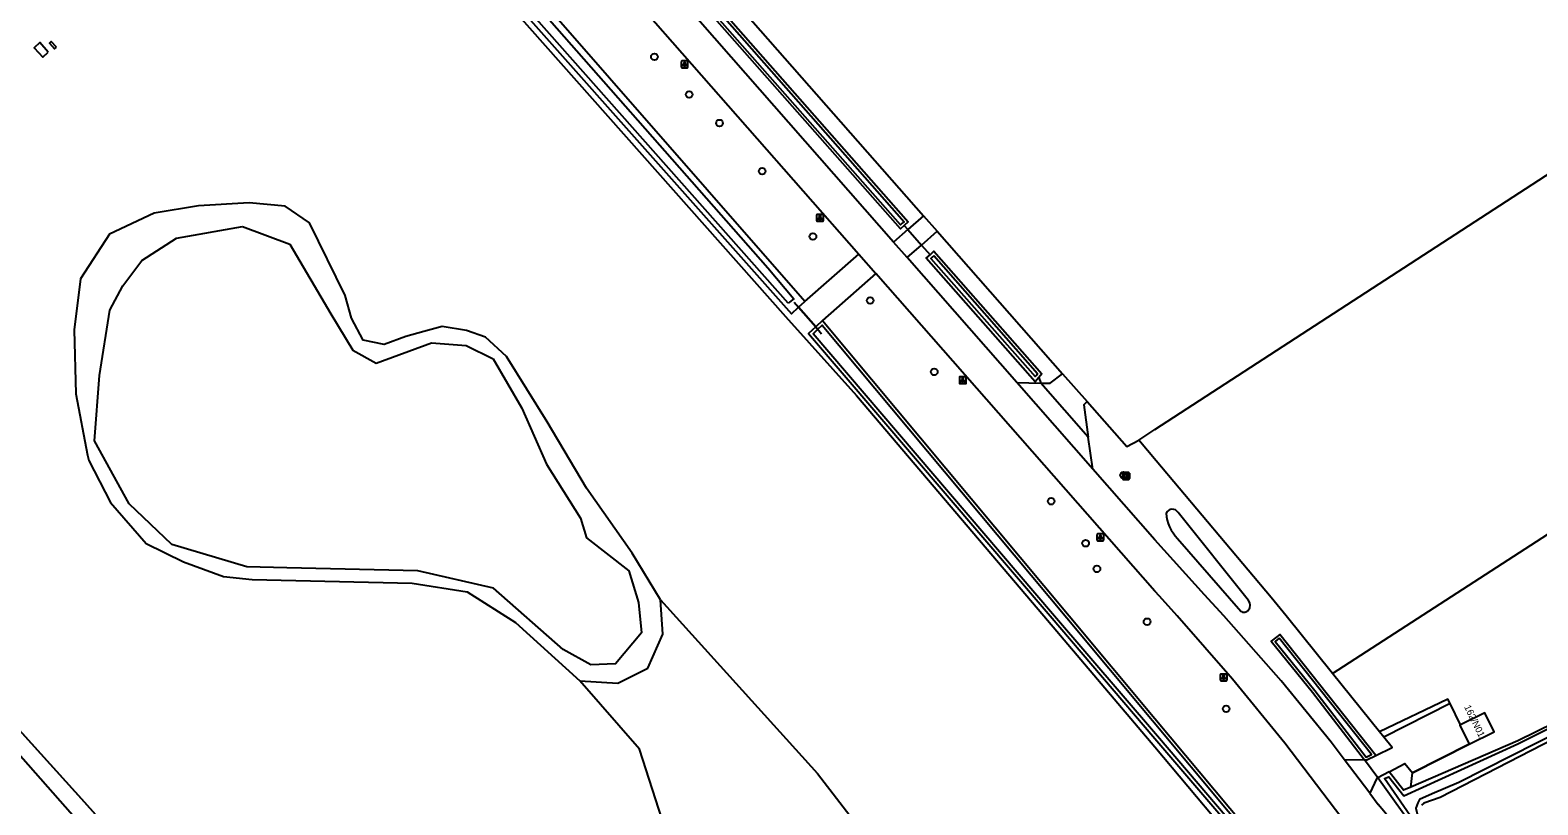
# Model space of a CAD drawing. Extents: x 156061 to 157804, y 383451 to 385640.
# Drawn here: x 157335.7 to 157555.9, y 383972.4 to 384085.5 of the extents above; entities that cross this region are included whole.
import ezdxf

# ---------------------------------------------------------------- set-up
doc = ezdxf.new("R2010")
doc.units = 0
for name, color, linetype in [('IMGEO_Berm_groen', 7, 'Continuous'), ('IMGEO_Boom', 7, 'Continuous'), ('IMGEO_Duiker', 7, 'Continuous'), ('IMGEO_Grasland_overig', 7, 'Continuous'), ('IMGEO_Groenvoorziening', 7, 'Continuous'), ('IMGEO_Haag', 7, 'Continuous'), ('IMGEO_Hek', 7, 'Continuous'), ('IMGEO_Lichtpunt', 7, 'Continuous'), ('IMGEO_Loofbos', 7, 'Continuous'), ('IMGEO_Meer_plas_ven_vijver', 7, 'Continuous'), ('IMGEO_Naaldbos', 7, 'Continuous'), ('IMGEO_Pand', 7, 'Continuous'), ('IMGEO_Pand_nummerreeks', 7, 'Continuous'), ('IMGEO_Rijbaan_lokaal_gesloten', 7, 'Continuous'), ('IMGEO_Rijbaan_lokaal_open', 7, 'Continuous'), ('IMGEO_Verklikker', 7, 'Continuous'), ('IMGEO_Waterloop', 7, 'Continuous')]:
    doc.layers.add(name, color=color, linetype=linetype)

msp = doc.modelspace()

# ---------------------------------------------------------------- linework, layer by layer
at = {"layer": 'IMGEO_Berm_groen'}
for points in [[(157463.38, 384056.98), (157462.83, 384056.5), (157343.68, 384191.47)], [(157317.96, 384189.64), (157344.19, 384159.18), (157364.55, 384136), (157393.61, 384102.92), (157399.11, 384096.66), (157446.05, 384043.69), (157456.41, 384032.18), (157483.79, 384000), (157500, 383980.87), (157519.27, 383957.9)], [(157448.89, 384045.9), (157391.84, 384111.13), (157390.82, 384110.23), (157389.32, 384108.91), (157446.91, 384044.08), (157447.97, 384045.05)], [(157463.38, 384056.98), (157463.91, 384056.38)], [(157463.91, 384056.38), (157461.84, 384054.56)], [(157463.91, 384056.38), (157465.9, 384054.13)], [(157448.89, 384045.9), (157456.76, 384052.82)], [(157463.82, 384052.3), (157465.9, 384054.13)], [(157465.9, 384054.13), (157467.16, 384052.71)], [(157483.03, 384034.79), (157482.52, 384034.17), (157466.6, 384052.22), (157467.16, 384052.71)], [(157459.26, 384049.98), (157451.47, 384043.13)], [(157450.46, 384042.19), (157447.97, 384045.05)], [(157450.46, 384042.19), (157449.42, 384041.22), (157484.69, 384000), (157500, 383982.12), (157520.38, 383958.3)], [(157451.47, 384043.13), (157487.5, 384000), (157500, 383985.04), (157521.88, 383958.85), (157530.15, 383962.42), (157532.92, 383958.91), (157532.95, 383957.92), (157532.22, 383957.33), (157531.69, 383956.9), (157531.35, 383957.26)], [(157479.83, 384034.07), (157483.33, 384033.99)], [(157483.03, 384034.79), (157483.33, 384033.99)], [(157490.28, 384026.1), (157483.33, 384033.99)], [(157490.12, 384031.28), (157489.62, 384030.82), (157490.28, 384026.1)], [(157490.12, 384031.28), (157495.9, 384024.71), (157497.66, 384025.67)], [(157490.93, 384021.43), (157490.28, 384026.1)], [(157525.95, 383991.61), (157519.18, 384000), (157517.01, 384002.7), (157500.2, 384022.65), (157497.66, 384025.67)], [(157532.29, 383979.64), (157518.23, 383997.3), (157516.98, 383996.33), (157523.02, 383988.86), (157530.64, 383978.98)], [(157532.83, 383983.08), (157525.95, 383991.61)]]:
    msp.add_lwpolyline(points, dxfattribs=at)
at = {"layer": 'IMGEO_Boom'}
for centre in [(157426.9, 384081.61), (157431.99, 384076.11), (157436.42, 384071.94), (157442.64, 384064.91), (157450.06, 384055.38), (157458.43, 384046.03), (157467.78, 384035.61), (157495.43, 384020.55), (157484.85, 384016.73), (157489.89, 384010.6), (157491.54, 384006.85), (157498.86, 383999.15), (157510.42, 383986.43)]:
    msp.add_circle(centre, 0.489, dxfattribs=at)
at = {"layer": 'IMGEO_Duiker'}
msp.add_lwpolyline([(157447.34, 384045.77), (157447.97, 384045.05), (157450.46, 384042.19), (157451.33, 384041.19)], dxfattribs=at)
at = {"layer": 'IMGEO_Grasland_overig'}
for points in [[(157466.22, 384058.41), (157463.91, 384056.38)], [(157466.22, 384058.41), (157468.2, 384056.16)], [(157465.9, 384054.13), (157468.2, 384056.16)], [(157447.97, 384045.05), (157448.89, 384045.9)], [(157451.47, 384043.13), (157450.46, 384042.19)], [(157483.33, 384033.99), (157484.7, 384033.96), (157486.53, 384035.35)], [(157486.53, 384035.35), (157490.12, 384031.28)]]:
    msp.add_lwpolyline(points, dxfattribs=at)
at = {"layer": 'IMGEO_Groenvoorziening'}
for points in [[(157375.38, 384222.59), (157376.59, 384220.76), (157342.51, 384199.14), (157412.58, 384119.43), (157466.22, 384058.41)], [(157344.9, 384192.66), (157463.98, 384057.5), (157463.38, 384056.98)], [(157497.66, 384025.67), (157500, 384027.19), (157642, 384119.41), (157643.26, 384117.4), (157752.8, 384188.65)], [(157338.37, 384082.3), (157337.13, 384083.67), (157336.32, 384082.91), (157337.56, 384081.55), (157338.37, 384082.3)], [(157339.56, 384083), (157338.8, 384083.82), (157338.55, 384083.59), (157339.31, 384082.77), (157339.56, 384083)], [(157525.95, 383991.61), (157642.66, 384067.03)], [(157427.78, 384002.36), (157423.67, 384009.14), (157417, 384018.64), (157411.26, 384028.33), (157405.29, 384037.84), (157402.23, 384040.67), (157399.47, 384041.67), (157395.89, 384042.26), (157393.24, 384041.49), (157390.58, 384040.79), (157387.45, 384039.61), (157384.39, 384040.23), (157382.66, 384043.44), (157381.76, 384046.77), (157376.54, 384057.37), (157372.96, 384059.82), (157367.71, 384060.27), (157360.32, 384059.84), (157353.83, 384058.77), (157347.34, 384055.73), (157343.08, 384049.2), (157342.15, 384041.74), (157342.41, 384032.41), (157344.13, 384023.44), (157344.28, 384022.68), (157347.47, 384016.55), (157352.67, 384010.55), (157358.11, 384007.87), (157363.98, 384005.74), (157368.14, 384005.33), (157391.54, 384004.75), (157399.57, 384003.53), (157406.64, 383999.04), (157416.03, 383990.5)], [(157468.2, 384056.16), (157486.53, 384035.35)], [(157467.16, 384052.71), (157467.74, 384053.23), (157483.49, 384035.34), (157483.03, 384034.79)], [(157656.19, 384033.53), (157590.21, 384000), (157553.01, 383981.76), (157549.75, 383980.34), (157537.39, 383975.02)], [(157656.19, 384033.53), (157656.8, 384032.66), (157593.24, 384000), (157541.68, 383973.51), (157539.29, 383972.68), (157538.96, 383972.37)], [(157542, 383963.16), (157538.56, 383967.99), (157532.58, 383976.37)], [(157537.39, 383975.02), (157536.33, 383974.56), (157534.2, 383977.23)], [(157537.39, 383975.02), (157537.64, 383977.09)]]:
    msp.add_lwpolyline(points, dxfattribs=at)
at = {"layer": 'IMGEO_Haag'}
for points in [[(157543.11, 383987.19), (157542.78, 383987.84), (157532.83, 383983.08)], [(157533.45, 383982.31), (157532.83, 383983.08)]]:
    msp.add_lwpolyline(points, dxfattribs=at)
at = {"layer": 'IMGEO_Hek'}
for points in [[(157376.59, 384220.76), (157342.51, 384199.14), (157412.58, 384119.43), (157466.22, 384058.41)], [(157500, 384027.19), (157642, 384119.41)], [(157466.22, 384058.41), (157468.2, 384056.16)], [(157468.2, 384056.16), (157486.53, 384035.35)], [(157286.32, 384037.05), (157293.19, 384028.12), (157297.01, 384023.54), (157304.07, 384015.72), (157311.43, 384008.18), (157319.02, 384000), (157343.68, 383972.81), (157358.66, 383956.01), (157373.77, 383939.34), (157386.41, 383926.07), (157399.25, 383913.04)], [(157486.53, 384035.35), (157490.12, 384031.28)], [(157490.12, 384031.28), (157495.9, 384024.71)], [(157497.66, 384025.67), (157500, 384027.19)], [(157495.9, 384024.71), (157497.66, 384025.67)], [(157500.2, 384022.65), (157497.66, 384025.67)], [(157519.18, 384000), (157517.01, 384002.7), (157500.2, 384022.65)], [(157525.95, 383991.61), (157519.18, 384000)], [(157532.83, 383983.08), (157525.95, 383991.61)], [(157543.11, 383987.19), (157542.78, 383987.84), (157532.83, 383983.08)], [(157544.65, 383984.1), (157543.11, 383987.19)], [(157545.89, 383981.26), (157537.64, 383977.09)]]:
    msp.add_lwpolyline(points, dxfattribs=at)
at = {"layer": 'IMGEO_Lichtpunt'}
for p, q in [((157430.82, 384080.92), (157430.82, 384080.11)), ((157430.82, 384080.92), (157430.82, 384080.11)), ((157431.72, 384081.01), (157430.91, 384081.01)), ((157431.72, 384081.01), (157430.91, 384081.01)), ((157430.91, 384080.01), (157431.72, 384080.01)), ((157430.91, 384080.01), (157431.72, 384080.01)), ((157431.81, 384080.11), (157431.81, 384080.92)), ((157431.81, 384080.11), (157431.81, 384080.92)), ((157450.59, 384058.51), (157450.59, 384057.7)), ((157450.59, 384058.51), (157450.59, 384057.7)), ((157451.49, 384058.61), (157450.69, 384058.61)), ((157451.49, 384058.61), (157450.69, 384058.61)), ((157450.69, 384057.61), (157451.49, 384057.61)), ((157450.69, 384057.61), (157451.49, 384057.61)), ((157451.59, 384057.7), (157451.59, 384058.51)), ((157451.59, 384057.7), (157451.59, 384058.51)), ((157472.35, 384034.91), (157471.54, 384034.91)), ((157472.35, 384034.91), (157471.54, 384034.91)), ((157471.45, 384034.81), (157471.45, 384034)), ((157471.45, 384034.81), (157471.45, 384034)), ((157471.54, 384033.91), (157472.35, 384033.91)), ((157471.54, 384033.91), (157472.35, 384033.91)), ((157472.44, 384034), (157472.44, 384034.81)), ((157472.44, 384034), (157472.44, 384034.81)), ((157491.53, 384011.88), (157491.53, 384011.07)), ((157491.53, 384011.88), (157491.53, 384011.07)), ((157492.43, 384011.97), (157491.63, 384011.97)), ((157492.43, 384011.97), (157491.63, 384011.97)), ((157491.63, 384010.97), (157492.43, 384010.97)), ((157491.63, 384010.97), (157492.43, 384010.97)), ((157492.53, 384011.07), (157492.53, 384011.88)), ((157492.53, 384011.07), (157492.53, 384011.88)), ((157509.55, 383991.41), (157509.55, 383990.61)), ((157509.55, 383991.41), (157509.55, 383990.61)), ((157510.45, 383991.51), (157509.64, 383991.51)), ((157510.45, 383991.51), (157509.64, 383991.51)), ((157510.55, 383990.61), (157510.55, 383991.41)), ((157510.55, 383990.61), (157510.55, 383991.41)), ((157509.64, 383990.51), (157510.45, 383990.51)), ((157509.64, 383990.51), (157510.45, 383990.51))]:
    msp.add_line(p, q, dxfattribs=at)
for points in [[(157431.19, 384080.58), (157431.23, 384080.55), (157431.04, 384080.29), (157431, 384080.32), (157431.19, 384080.58)], [(157431.29, 384080.53), (157431.34, 384080.53), (157431.34, 384080.21), (157431.29, 384080.21), (157431.29, 384080.53)], [(157431.4, 384080.55), (157431.44, 384080.58), (157431.63, 384080.32), (157431.59, 384080.29), (157431.4, 384080.55)], [(157450.97, 384058.17), (157451, 384058.15), (157450.82, 384057.88), (157450.78, 384057.91), (157450.97, 384058.17)], [(157451.07, 384058.13), (157451.11, 384058.13), (157451.11, 384057.8), (157451.07, 384057.8), (157451.07, 384058.13)], [(157451.18, 384058.15), (157451.22, 384058.17), (157451.4, 384057.91), (157451.36, 384057.88), (157451.18, 384058.15)], [(157471.82, 384034.47), (157471.86, 384034.45), (157471.67, 384034.18), (157471.63, 384034.21), (157471.82, 384034.47)], [(157471.92, 384034.43), (157471.97, 384034.43), (157471.97, 384034.1), (157471.92, 384034.1), (157471.92, 384034.43)], [(157472.03, 384034.45), (157472.07, 384034.47), (157472.26, 384034.21), (157472.22, 384034.18), (157472.03, 384034.45)], [(157491.91, 384011.54), (157491.95, 384011.51), (157491.76, 384011.25), (157491.72, 384011.28), (157491.91, 384011.54)], [(157492.01, 384011.49), (157492.06, 384011.49), (157492.06, 384011.17), (157492.01, 384011.17), (157492.01, 384011.49)], [(157492.12, 384011.51), (157492.16, 384011.54), (157492.34, 384011.28), (157492.31, 384011.25), (157492.12, 384011.51)], [(157509.92, 383991.08), (157509.96, 383991.05), (157509.77, 383990.79), (157509.74, 383990.81), (157509.92, 383991.08)], [(157510.02, 383991.03), (157510.07, 383991.03), (157510.07, 383990.71), (157510.02, 383990.71), (157510.02, 383991.03)], [(157510.13, 383991.05), (157510.17, 383991.08), (157510.36, 383990.81), (157510.32, 383990.79), (157510.13, 383991.05)]]:
    msp.add_lwpolyline(points, dxfattribs=at)
for centre in [(157431.32, 384080.71), (157451.09, 384058.31), (157471.95, 384034.61), (157492.03, 384011.67), (157510.05, 383991.21)]:
    msp.add_circle(centre, 0.0994, dxfattribs=at)
for centre, start, end in [((157430.91, 384080.92), 90, 180), ((157430.91, 384080.92), 90, 180), ((157430.91, 384080.11), 180, 270), ((157430.91, 384080.11), 180, 270), ((157431.72, 384080.92), 0, 90), ((157431.72, 384080.92), 0, 90), ((157431.72, 384080.11), 270, 0), ((157431.72, 384080.11), 270, 360), ((157450.69, 384058.51), 90, 180), ((157450.69, 384058.51), 90, 180), ((157450.69, 384057.7), 180, 270), ((157450.69, 384057.7), 180, 270), ((157451.49, 384058.51), 0, 90), ((157451.49, 384058.51), 0, 90), ((157451.49, 384057.7), 270, 0), ((157451.49, 384057.7), 270, 360), ((157471.54, 384034.81), 90, 180), ((157471.54, 384034.81), 90, 180), ((157472.35, 384034.81), 0, 90), ((157472.35, 384034.81), 0, 90), ((157471.54, 384034), 180, 270), ((157471.54, 384034), 180, 270), ((157472.35, 384034), 270, 0), ((157472.35, 384034), 270, 360), ((157491.63, 384011.88), 90, 180), ((157491.63, 384011.88), 90, 180), ((157491.63, 384011.07), 180, 270), ((157491.63, 384011.07), 180, 270), ((157492.43, 384011.88), 0, 90), ((157492.43, 384011.88), 0, 90), ((157492.43, 384011.07), 270, 0), ((157492.43, 384011.07), 270, 360), ((157509.64, 383991.41), 90, 180), ((157509.64, 383991.41), 90, 180), ((157510.45, 383991.41), 0, 90), ((157510.45, 383991.41), 0, 90), ((157509.64, 383990.61), 180, 270), ((157509.64, 383990.61), 180, 270), ((157510.45, 383990.61), 270, 0), ((157510.45, 383990.61), 270, 360)]:
    msp.add_arc(centre, 0.0946, start, end, dxfattribs=at)
at = {"layer": 'IMGEO_Loofbos'}
for points in [[(157399.25, 383913.04), (157386.41, 383926.07), (157373.77, 383939.34), (157358.66, 383956.01), (157343.68, 383972.81), (157319.02, 384000), (157311.43, 384008.18), (157304.07, 384015.72), (157297.01, 384023.54), (157293.19, 384028.12), (157286.32, 384037.05)], [(157288.58, 384031.37), (157316.26, 384000), (157389.92, 383916.52), (157394.32, 383912.05), (157396.72, 383911.03)]]:
    msp.add_lwpolyline(points, dxfattribs=at)
at = {"layer": 'IMGEO_Meer_plas_ven_vijver'}
msp.add_lwpolyline([(157366.73, 384056.82), (157373.67, 384054.28), (157379.64, 384044.1), (157382.88, 384038.8), (157386.26, 384036.87), (157394.33, 384039.84), (157399.39, 384039.46), (157403.37, 384037.54), (157407.56, 384030.32), (157411.16, 384022.15), (157416.12, 384014.25), (157417.01, 384011.38), (157423.19, 384006.58), (157424.6, 384001.94), (157425.03, 383997.52), (157421.21, 383992.99), (157417.6, 383992.87), (157413.57, 383995.11), (157403.38, 384004.03), (157392.34, 384006.58), (157373.24, 384007), (157367.4, 384007.17), (157356.4, 384010.4), (157350.18, 384016.34), (157345.14, 384025.53), (157345.88, 384035.11), (157347.35, 384044.62), (157349.27, 384048.16), (157352.02, 384051.87), (157357.11, 384055.13), (157366.73, 384056.82)], dxfattribs=at)
at = {"layer": 'IMGEO_Naaldbos'}
for points in [[(157416.03, 383990.5), (157421.54, 383990.17), (157425.96, 383992.38), (157428.16, 383997.33), (157427.78, 384002.36)], [(157427.78, 384002.36), (157450.71, 383977), (157457.73, 383967.9), (157453.38, 383965.1), (157446.36, 383961.6), (157438.21, 383958.78), (157432.13, 383957.26), (157425.98, 383955.9), (157425.19, 383960), (157429.47, 383965.92), (157424.72, 383980.52), (157416.03, 383990.5)]]:
    msp.add_lwpolyline(points, dxfattribs=at)
at = {"layer": 'IMGEO_Pand'}
for points in [[(157545.89, 383981.26), (157549.57, 383983.08), (157548.18, 383985.84), (157544.65, 383984.1)], [(157544.65, 383984.1), (157544.52, 383984.04), (157545.89, 383981.26)]]:
    msp.add_lwpolyline(points, dxfattribs=at)
at = {"layer": 'IMGEO_Rijbaan_lokaal_gesloten'}
for points in [[(157328.46, 384198.78), (157342.96, 384182.28), (157456.76, 384052.82)], [(157461.84, 384054.56), (157351.29, 384180.48), (157340.41, 384192.86)], [(157456.76, 384052.82), (157459.26, 384049.98)], [(157463.82, 384052.3), (157461.84, 384054.56)], [(157479.83, 384034.07), (157463.82, 384052.3)], [(157535.32, 383959.69), (157530.89, 383965.44), (157530.5, 383965.93), (157527.33, 383970.45), (157519, 383981.4), (157511.33, 383990.78), (157503.27, 384000), (157500.68, 384002.86), (157500, 384003.63), (157459.26, 384049.98)], [(157490.93, 384021.43), (157479.83, 384034.07)], [(157527.64, 383979.04), (157525.74, 383981.55), (157518.43, 383990.52), (157510.09, 384000), (157507.25, 384003.05), (157500, 384011.09), (157490.93, 384021.43)], [(157531.38, 383974.1), (157527.64, 383979.04)], [(157531.38, 383974.1), (157532.61, 383972.47)]]:
    msp.add_lwpolyline(points, dxfattribs=at)
msp.add_arc((157379.41, 383843.74), 200.11, 28.0956, 40.0394, dxfattribs=at)
at = {"layer": 'IMGEO_Rijbaan_lokaal_open'}
for points in [[(157543.11, 383987.19), (157533.45, 383982.31)], [(157544.65, 383984.1), (157543.11, 383987.19)], [(157532.29, 383979.64), (157534.64, 383980.79), (157533.45, 383982.31)], [(157537.64, 383977.09), (157545.89, 383981.26)], [(157527.64, 383979.04), (157530.64, 383978.98)], [(157530.64, 383978.98), (157530.94, 383978.98), (157532.29, 383979.64)], [(157532.58, 383976.37), (157530.64, 383978.98)], [(157534.2, 383977.23), (157536.53, 383978.45), (157537.64, 383977.09)], [(157532.58, 383976.37), (157532.42, 383976.29), (157531.38, 383974.1)], [(157534.2, 383977.23), (157532.58, 383976.37)]]:
    msp.add_lwpolyline(points, dxfattribs=at)
at = {"layer": 'IMGEO_Verklikker'}
for p, q in [((157495.3, 384020.03), (157495.3, 384020.83)), ((157495.3, 384020.83), (157495.3, 384020.03)), ((157495.4, 384020.93), (157496.19, 384020.93)), ((157496.19, 384020.93), (157495.4, 384020.93)), ((157496.19, 384019.93), (157495.4, 384019.93)), ((157495.4, 384019.93), (157496.19, 384019.93)), ((157496.29, 384020.83), (157496.29, 384020.03)), ((157496.29, 384020.03), (157496.29, 384020.83))]:
    msp.add_line(p, q, dxfattribs=at)
for points in [[(157495.4, 384020.66), (157496.19, 384020.66), (157496.19, 384020.19), (157495.4, 384020.19), (157495.4, 384020.66)], [(157495.47, 384020.59), (157495.47, 384020.26), (157496.13, 384020.26), (157496.13, 384020.59), (157495.47, 384020.59)]]:
    msp.add_lwpolyline(points, dxfattribs=at)
for centre, start, end in [((157495.4, 384020.83), 90, 180), ((157495.4, 384020.83), 90, 180), ((157495.4, 384020.03), 180, 270), ((157495.4, 384020.03), 180, 270), ((157496.19, 384020.83), 0, 90), ((157496.19, 384020.83), 360, 90), ((157496.19, 384020.03), 270, 0), ((157496.19, 384020.03), 270, 0)]:
    msp.add_arc(centre, 0.1, start, end, dxfattribs=at)
at = {"layer": 'IMGEO_Waterloop'}
for points in [[(157344.59, 384192.37), (157463.38, 384057.54), (157463.1, 384057.3), (157462.87, 384057.1), (157385.2, 384145.03), (157343.99, 384191.76)], [(157446.42, 384045.66), (157404.4, 384093.13), (157390.98, 384108.29), (157392.43, 384109.4), (157403.68, 384095.98), (157443.49, 384050.82), (157447.27, 384046.27), (157446.42, 384045.66)], [(157467.7, 384052.53), (157467.48, 384052.34), (157467.3, 384052.18), (157482.51, 384034.93), (157482.65, 384035.1), (157482.84, 384035.33), (157467.7, 384052.53)], [(157520.75, 383958.62), (157500.37, 383982.43), (157485.06, 384000.31), (157450.08, 384041.18), (157450.78, 384041.83), (157451.42, 384042.43), (157487.13, 383999.69), (157499.63, 383984.73)], [(157513.66, 384002.23), (157503.4, 384015.1)], [(157503.29, 384011.29), (157512.54, 384000.71)], [(157549.77, 383953.21), (157537.79, 383970.15), (157533.55, 383976.27), (157534.18, 383976.52), (157536.35, 383973.72), (157553, 383981.32), (157590.9, 384000.13)], [(157518.16, 383996.73), (157517.56, 383996.26), (157523.34, 383989.11), (157530.84, 383979.39), (157530.85, 383979.39), (157531.65, 383979.78), (157518.16, 383996.73)], [(157499.63, 383984.73), (157521.74, 383958.27)], [(157559.58, 383983.38), (157544.42, 383975.69), (157540.51, 383974.02), (157538.66, 383973.21), (157538.39, 383972.7), (157538.13, 383971.94), (157538.33, 383971.09), (157545.65, 383961.38), (157551.34, 383953.49), (157553.33, 383951.7), (157563.27, 383945.93)]]:
    msp.add_lwpolyline(points, dxfattribs=at)
for centre, radius, start, end in [((157502.55, 384014.57), 1, 31.6822, 156.9523), ((157507.72, 384015.51), 6.11, 185.0653, 223.6347), ((157512.91, 384001.54), 1.01, 318.1974, 42.3929), ((157513.03, 384001.28), 0.758, 229.1685, 326.9357)]:
    msp.add_arc(centre, radius, start, end, dxfattribs=at)

# ---------------------------------------------------------------- texts
at = {"layer": 'IMGEO_Pand_nummerreeks'}
msp.add_text('162/N01', height=1, rotation=296.0935, dxfattribs=at).set_placement((157545.14, 383986.71))

doc.saveas('drawing.dxf')
